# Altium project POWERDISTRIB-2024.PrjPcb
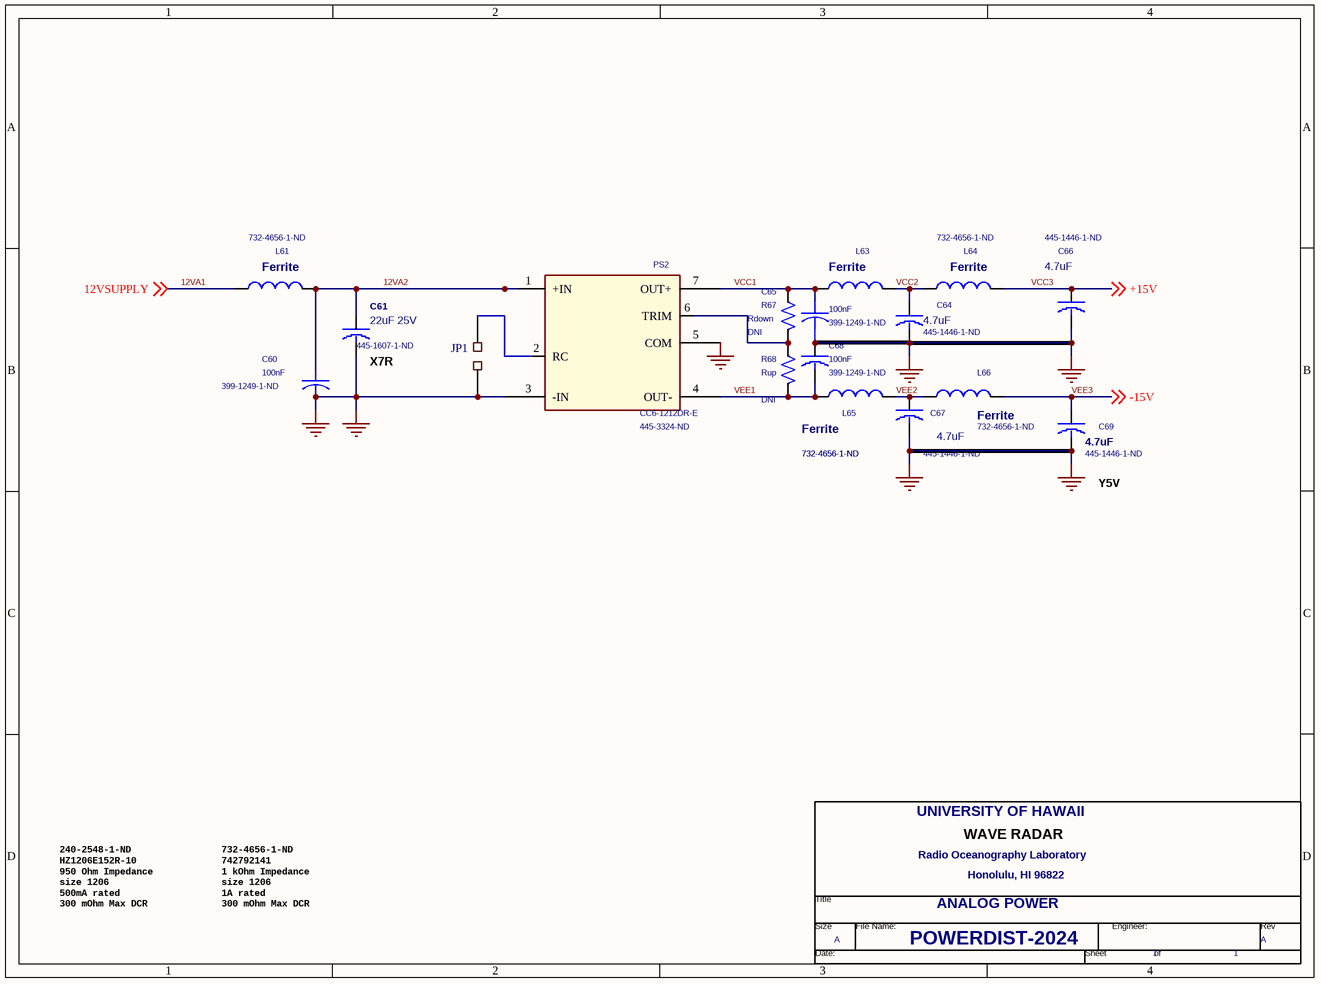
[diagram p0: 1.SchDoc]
2 sheets, 61 parts. Net scope: global (net labels, ports and power ports of the same name join across sheets).
Board file: POWERDISTRIB-2024.PcbDoc
Sheets:
  1.SchDoc
  2.SchDoc

## Sheet 1.SchDoc
size 246 x 182 mm; Organization: Altium Limited; Address1: L3, 12a Rodborough Rd; Address2: Frenchs Forest; Address3: NSW; Address4: Australia 2086

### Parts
(Parts that share a designator on the sheet are numbered #1, #2 ... from top to bottom, then left to right.)
*#1  Doc: POWERDIST-2024  RevCode: A  Title: ANALOG POWER  OrgName: UNIVERSITY OF HAWAII  OrgAddr1: Radio Oceanography Laboratory  OrgAddr3: Honolulu, HI 96822  Page Number: 1  (hidden comment: HWRadar)  (graphical)
C60  100nF  DK Stock: 399-1249-1-ND  [1206]
C61  22uF 25V  DK Stock: 445-1607-1-ND  [1812]
C64  4.7uF  DK Stock: 445-1446-1-ND  [1812]
C65  100nF  DK Stock: 399-1249-1-ND  [1206]
C66  4.7uF  DK Stock: 445-1446-1-ND  [1812]
C67  4.7uF  DK Stock: 445-1446-1-ND  [1812]
C68  100nF  DK Stock: 399-1249-1-ND  [1206]
C69  4.7uF  DK Stock: 445-1446-1-ND  [1812]
JP1  (no value)  [2X2.54]
L61  Ferrite  DK Stock: 732-4656-1-ND  [1206]
L63  Ferrite  DK Stock: 732-4656-1-ND  [1206]
L64  Ferrite  DK Stock: 732-4656-1-ND  [1206]
L65  Ferrite  DK Stock: 732-4656-1-ND  [1206]
L66  Ferrite  DK Stock: 732-4656-1-ND  [1206]
PS2  CC6-1212DR-E  DK Stock: 445-3324-ND  [DCDC-CC6/B]
R67  Rdown  DK Stock: DNI  [1206]
R68  Rup  DK Stock: DNI  [1206]

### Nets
GND: C60.2 C61.2 C64.2 C65.2 C66.2 C67.2 C68.1 C69.2 JP1.1 PS2.3(-IN) PS2.5(COM)
12VA1: L61.1 ; off-sheet 12VSUPPLY  [also labelled 12VSUPPLY]
12VA2: C60.1 C61.1 L61.2 PS2.1(+IN)
VCC1: C65.1 L63.1 PS2.7(OUT+) R67.1
VCC2: C64.1 L63.2 L64.1
VCC3: C66.1 L64.2 ; off-sheet +15V  [also labelled +15V]
VEE1: C68.2 L65.1 PS2.4(OUT-) R68.2
VEE2: C67.1 L65.2 L66.1
VEE3: C69.1 L66.2 ; off-sheet -15V  [also labelled -15V]
NetJP1_2: JP1.2 PS2.2(RC)
NetPS2_6: PS2.6(TRIM) R67.2 R68.1

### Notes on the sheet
- (near C61) X7R
- (near C69) Y5V
- 240-2548-1-ND
  HZ1206E152R-10
  950 Ohm Impedance
  size 1206
  500mA rated
  300 mOhm Max DCR
- 732-4656-1-ND
  742792141
  1 kOhm Impedance
  size 1206
  1A rated
  300 mOhm Max DCR

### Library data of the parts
*#1 = HWRadar: Engineer:: <ENG>; OrgAddr2: 2525 Correa Road
C60 C65 = CAP_SHORT
C61 C64 C66-C69 = C1206
JP1 = STRAP
L61 L63-L66 = INDUCTOR
PS2 = CONV +-15V_1
R67 R68 = R1206

## Sheet 2.SchDoc
size 386 x 246 mm; Organization: Altium Limited; Address1: L3, 12a Rodborough Rd; Address2: Frenchs Forest; Address3: NSW; Address4: Australia 2086
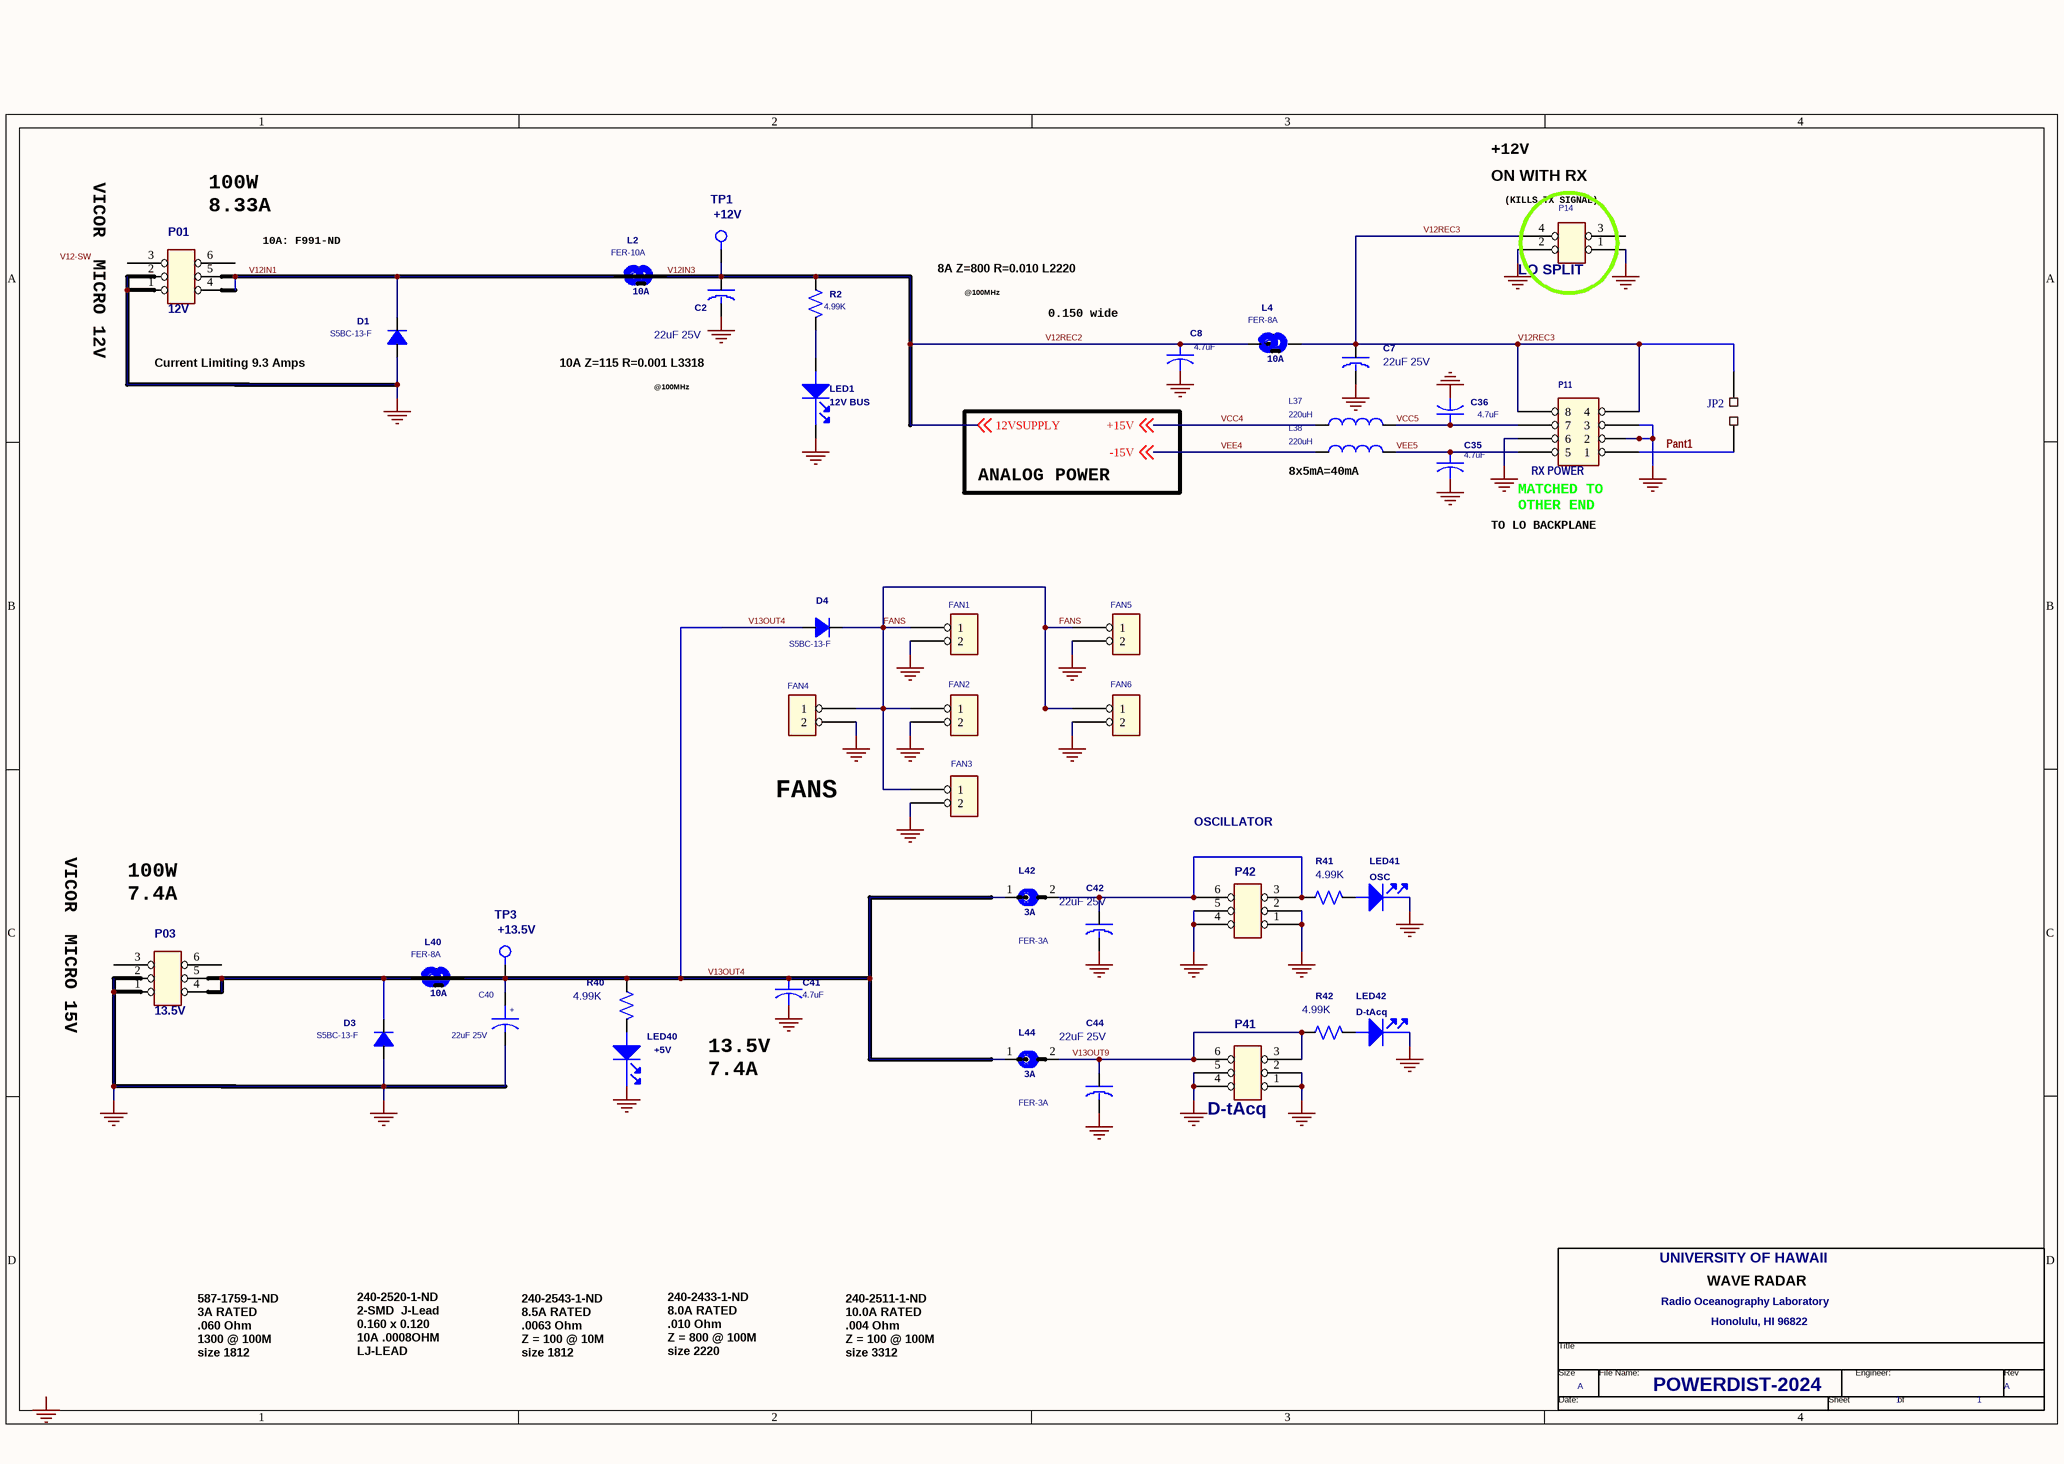
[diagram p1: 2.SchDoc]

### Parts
(Parts that share a designator on the sheet are numbered #1, #2 ... from top to bottom, then left to right.)
*#2  Doc: POWERDIST-2024  RevCode: A  OrgName: UNIVERSITY OF HAWAII  OrgAddr1: Radio Oceanography Laboratory  OrgAddr3: Honolulu, HI 96822  Page Number: 1  (hidden comment: HWRadar)  (graphical)
C2  22uF 25V  [1812]
C7  22uF 25V  [1812]
C8  4.7uF  [1812]
C35  4.7uF  [1812]
C36  4.7uF  [1812]
C40  22uF 25V  [1812]
C41  4.7uF  [1812]
C42  22uF 25V  [1812]
C44  22uF 25V  [1812]
D1  S5BC-13-F  [SMC]
D3  S5BC-13-F  [SMC]
D4  S5BC-13-F  [SMC]
FAN1  FAN1  [SIP2-SHRD]  (value not drawn)
FAN2  FAN2  [SIP2-SHRD]  (value not drawn)
FAN3  FAN3  [SIP2-SHRD]  (value not drawn)
FAN4  FAN4  [SIP2-SHRD]  (value not drawn)
FAN5  FAN1  [SIP2-SHRD]  (value not drawn)
FAN6  FAN2  [SIP2-SHRD]  (value not drawn)
JP2  (no value)  [2X2.54]
L2  FER-10A  [l3318]
L4  FER-8A  [2220]
L37  220uH  [1812]
L38  220uH  [1812]
L40  FER-8A  [2220]
L42  FER-3A  [1812]
L44  FER-3A  [1812]
LED1  12V BUS  [LED1206]
LED40  +5V  [LED1206]
LED41  D-tAcq  [LED1206]
LED42  OSC  [LED1206]
P01  12V  [MFTJR2X3]
P03  13.5V  [MFTJR2X3]
P11  RX POWER  [MFTJR2X4]
P14  LO SPLIT  [MFTJR2X2]
P41  D-tAcq  [MFTJR2X3]
P42  OSCILLATOR  [MFTJR2X3]
R2  4.99K  [1206]
R40  4.99K  [1206]
R41  4.99K  [1206]
R42  4.99K  [1206]
TP1  +12V  [TP]
TP3  +13.5V  [TP]

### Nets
GND: C2.2 C7.2 C8.2 C35.2 C36.2 C40.2 C41.2 C42.2 C44.2 D1.A(ANOD) D3.A(ANOD) FAN1.2 FAN2.2 FAN3.2 FAN4.2 FAN5.2 FAN6.2 LED1.2(CATHODE) LED40.2(CATHODE) LED41.2(CATHODE) LED42.2(CATHODE) P01.1 P01.2 P03.1 P03.2 P11.2 P11.3 P11.6 P14.1 P14.2 P41.1 P41.2 P41.4 P41.5 P42.1 P42.2 P42.4 P42.5
12VSUPPLY: C2.1 C8.1 L2.2(L2) L4.1(L1) R2.1 TP1.TP ; off-sheet 12VSUPPLY  [also labelled V12IN3, V12REC2]  [project net 12VA1]
+15V: L37.1 ; off-sheet +15V  [also labelled VCC4]  [project net VCC3]
-15V: L38.1 ; off-sheet -15V  [also labelled VEE4]  [project net VEE3]
FANS: D4.K(CATH) FAN1.1 FAN2.1 FAN3.1 FAN4.1 FAN5.1 FAN6.1
Pant1: JP2.1 P11.1
V12IN1: D1.K(CATH) L2.1(L1) P01.4 P01.5
V12REC3: C7.1 JP2.2 L4.2(L2) P11.4 P11.8 P14.4
V13OUT4: C40.1 C41.1 D4.A(ANOD) L40.2(L2) L42.1(L1) L44.1(L1) R40.1 TP3.TP
V13OUT9: C44.1 L44.2(L2) P41.3 P41.6 R42.1
VCC5: C36.1 L37.2 P11.7
VEE5: C35.1 L38.2 P11.5
NetC42_1: C42.1 L42.2(L2) P42.3 P42.6 R41.1
NetD3_K: D3.K(CATH) L40.1(L1) P03.4 P03.5
NetLED1_1: LED1.1(ANODE) R2.2
NetLED40_1: LED40.1(ANODE) R40.2
NetLED41_1: LED41.1(ANODE) R41.2
NetLED42_1: LED42.1(ANODE) R42.2

Not connected (* = marked no-connect by the designer): P01 3 6; P03 3 6; P14 3

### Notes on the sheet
- +12V
- VICOR  MICRO 12V
- (near P01) 100W
  8.33A
- (near P14) ON WITH RX
- (near P14) (KILLS TX SIGNAL)
- 10A: F991-ND
- 8A Z=800 R=0.010 L2220
- @100MHz
- Current Limiting 9.3 Amps
- 10A Z=115 R=0.001 L3318
- 0.150 wide
- ANALOG POWER
- (near L38) 8x5mA=40mA
- TO LO BACKPLANE
- (near P11) MATCHED TO
  OTHER END
- FANS
- VICOR  MICRO 15V
- (near P03) 100W
  7.4A
- (near C41) 13.5V
  7.4A
- 587-1759-1-ND
  3A RATED
  .060 Ohm
  1300 @ 100M
  size 1812
- 240-2520-1-ND
  2-SMD  J-Lead
  0.160 x 0.120
  10A .0008OHM
  LJ-LEAD
- 240-2543-1-ND
  8.5A RATED
  .0063 Ohm
  Z = 100 @ 10M
  size 1812
- 240-2433-1-ND
  8.0A RATED
  .010 Ohm
  Z = 800 @ 100M
  size 2220
- 240-2511-1-ND
  10.0A RATED
  .004 Ohm
  Z = 100 @ 100M
  size 3312
- Labels drawn without touching a wire or pin: GND, V12-SW

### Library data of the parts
*#2 = HWRadar: as *#1 on sheet 1
C2 C7 C42 C44 = C1206: DK Stock: 445-1607-1-ND
C8 C35 C36 C41 = CAP1206: DK Stock: 445-1446-1-ND
C40 = CAPACITOR POL: DK Stock: 445-1607-1-ND
D1 D3 D4 = DIODE2: DK Stock: S5BC-FDICT-ND
FAN1-FAN6 = HEADER 2_0: DK Stock: A30931-ND
JP2 = STRAP
L2 = FERRITE1812_0: DK Stock: 240-2511-1-ND
L4 L40 = FERRITE1812_0: DK Stock: 240-2433-1-ND
L37 L38 = INDUCTOR: DK Stock: DN7942CT-ND
L42 L44 = FERRITE_0: DK Stock: 587-1759-1-ND
LED1 = LED_1: DK Stock: 754-1445-1-ND
LED40-LED42 = LED_0: DK Stock: 754-1445-1-ND
P01 P03 P41 P42 = HEADER 3X2_0: DK Stock: WM3802-ND
P11 = HEADER 4X2_0: DK Stock: WM3803-ND
P14 = HEADER 2X2_5: DK Stock: WM3801-ND
R2 = RES1206: DK Stock: 311-4..99KFRCT-ND
R40-R42 = RES1206: DK Stock: 311-2.49KFRCT-ND
TP1 TP3 = TP: DK Stock: NS

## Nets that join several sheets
GND: 1 (11 pins), 2 (38 pins)
12VA1: 1 (L61.1), 2 (6 pins)
VCC3: 1 (C66.1 L64.2), 2 (L37.1)
VEE3: 1 (C69.1 L66.2), 2 (L38.1)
